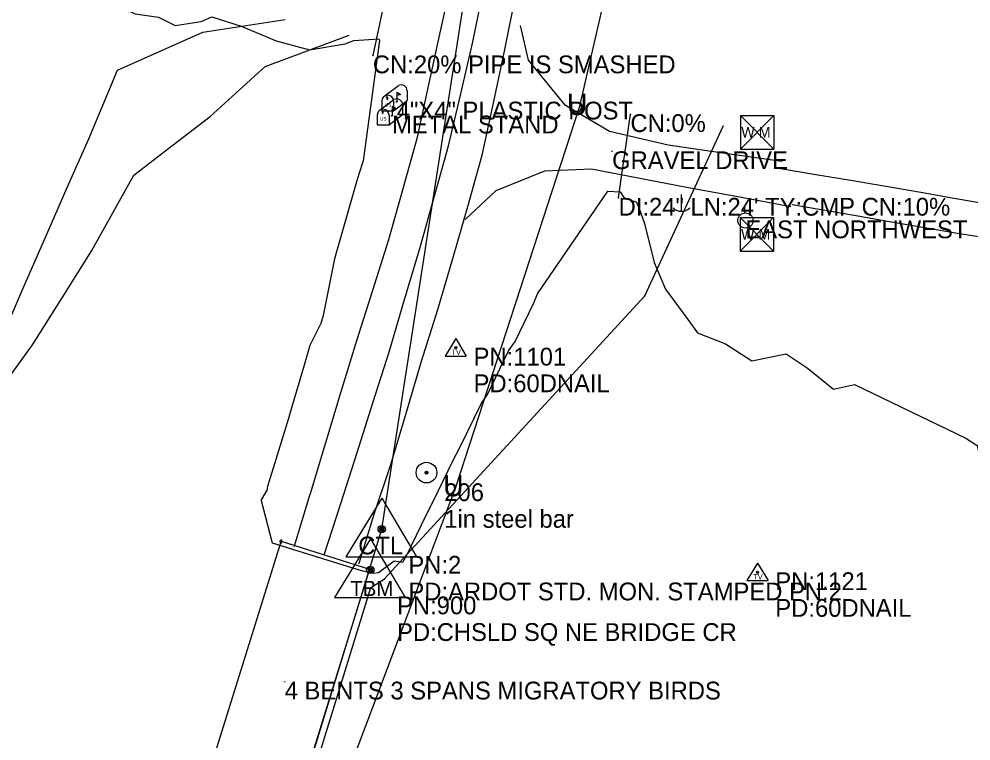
# Model space of a CAD drawing. Extents: x 1383673 to 1386849, y 1973501 to 1978801.
# Drawn here: x 1385039.6 to 1385307.2, y 1974767.7 to 1974970.6 of the extents above; entities that cross this region are included whole.
import ezdxf

# ---------------------------------------------------------------- set-up
doc = ezdxf.new("R2010")
doc.units = 0
for name, color, linetype in [('56', 7, 'Continuous'), ('8', 7, 'Continuous'), ('B-Super-Deck', 7, 'Continuous'), ('Default', 7, 'Continuous'), ('Level 42', 7, 'Continuous'), ('Level 6', 7, 'Continuous'), ('Level 62', 7, 'Continuous'), ('Level 8', 7, 'Continuous'), ('MOT_Barrier Wall Stage 3', 7, 'Continuous'), ('MOT_Drums_Stage 1', 7, 'Continuous'), ('MOT_Stage 2_Grading Hatch', 7, 'Continuous'), ('MOT_Stage 2_Pavement Hatch', 7, 'Continuous'), ('MOT_TIAB_Stage 3', 7, 'Continuous'), ('P_TC_Signs_Permanent', 7, 'Continuous'), ('R_Annotation', 7, 'Continuous'), ('R_Draft', 7, 'Continuous'), ('R_Guardrail', 7, 'Continuous'), ('R_Horz Alg', 7, 'Continuous'), ('R_Horz Alg Stationing', 7, 'Continuous'), ('R_Proposed Const Limits', 7, 'Continuous'), ('R_Traffic Signs', 7, 'Continuous'), ('S_BRIDGE', 7, 'Continuous'), ('S_EDGE_PAVEMENT', 7, 'Continuous'), ('S_STREAM', 7, 'Continuous'), ('S_WATER_UTILITIES', 7, 'Continuous'), ('SIGNS', 7, 'Continuous'), ('SIGNS_TX', 7, 'Continuous')]:
    doc.layers.add(name, color=color, linetype=linetype)

msp = doc.modelspace()

# ---------------------------------------------------------------- linework, layer by layer
at = {"layer": '56'}
for p, q in [((1385225.77, 1974921.3), (1385225.77, 1974916.57)), ((1385243.68, 1974916.15), (1385243.68, 1974918.26))]:
    msp.add_line(p, q, dxfattribs=at)
msp.add_circle((1385243.8, 1974914.01), 2.13, dxfattribs=at)
msp.add_arc((1385225.83, 1974920), 3.41, 226.3972, 313.6028, dxfattribs=at)
at = {"layer": '8'}
for points in [[(1385113.31, 1974823.83), (1385113.31, 1974824.33), (1385113.31, 1974823.83), (1385112.81, 1974823.83), (1385113.31, 1974823.83), (1385113.31, 1974823.33), (1385113.31, 1974823.83), (1385113.81, 1974823.83)], [(1385113.31, 1974823.73), (1385113.31, 1974824.23), (1385113.31, 1974823.73), (1385112.81, 1974823.73), (1385113.31, 1974823.73), (1385113.31, 1974823.23), (1385113.31, 1974823.73), (1385113.81, 1974823.73)], [(1385138.17, 1974815.97), (1385138.17, 1974816.47), (1385138.17, 1974815.97), (1385137.67, 1974815.97), (1385138.17, 1974815.97), (1385138.17, 1974815.47), (1385138.17, 1974815.97), (1385138.67, 1974815.97)]]:
    msp.add_lwpolyline(points, dxfattribs=at)
at = {"layer": 'B-Super-Deck'}
msp.add_lwpolyline([(1385125.5, 1974820.2), (1385125.52, 1974820.28), (1385125.52, 1974820.28), (1385130.06, 1974834.4), (1385130.08, 1974834.48), (1385134.67, 1974848.76), (1385139.2, 1974863.06), (1385143.72, 1974877.37), (1385147.99, 1974891.75), (1385152.25, 1974906.13), (1385156.31, 1974920.57), (1385160.37, 1974935.01), (1385163.79, 1974949.62), (1385167.22, 1974964.22), (1385170.2, 1974978.92)], dxfattribs=at)
at = {"layer": 'Level 42'}
for p, q in [((1385142.16, 1974948.83), (1385146.3, 1974951.93)), ((1385145.78, 1974950.11), (1385145.78, 1974947.4)), ((1385148.73, 1974950.46), (1385148.73, 1974947.75)), ((1385140.87, 1974944.89), (1385145, 1974948)), ((1385141.61, 1974947.55), (1385141.61, 1974944.84)), ((1385144.93, 1974944.84), (1385148.73, 1974947.75)), ((1385144.93, 1974947.55), (1385144.93, 1974944.84)), ((1385141.61, 1974944.84), (1385144.93, 1974944.84)), ((1385144.48, 1974946.18), (1385144.48, 1974943.47)), ((1385147.43, 1974946.53), (1385147.43, 1974943.81)), ((1385140.31, 1974943.62), (1385140.31, 1974940.9)), ((1385143.64, 1974940.9), (1385147.43, 1974943.81)), ((1385143.64, 1974943.62), (1385143.64, 1974940.9)), ((1385140.31, 1974940.9), (1385143.64, 1974940.9))]:
    msp.add_line(p, q, dxfattribs=at)
for points in [[(1385145.78, 1974950.11), (1385146.89, 1974949.45), (1385145.78, 1974949.1)], [(1385142.79, 1974948.67), (1385143.02, 1974948.53), (1385143.02, 1974948.14), (1385143.32, 1974948.14), (1385143.32, 1974948.5), (1385143.13, 1974948.75), (1385142.79, 1974948.69)], [(1385141.5, 1974944.73), (1385141.72, 1974944.6), (1385141.72, 1974944.21), (1385142.02, 1974944.21), (1385142.02, 1974944.57), (1385141.83, 1974944.82), (1385141.5, 1974944.76)], [(1385144.48, 1974946.18), (1385145.59, 1974945.52), (1385144.48, 1974945.17)]]:
    msp.add_lwpolyline(points, dxfattribs=at)
for centre, end in [((1385147.07, 1974950.46), 117.5718), ((1385143.27, 1974947.55), 180), ((1385145.77, 1974946.53), 117.5718), ((1385141.97, 1974943.62), 180)]:
    msp.add_arc(centre, 1.66, 0, end, dxfattribs=at)
for centre in [(1385145.78, 1974947.4), (1385144.48, 1974943.47)]:
    msp.add_ellipse(centre, major_axis=(0.145, 0.132), ratio=0.564646, dxfattribs=at)
at = {"layer": 'Level 6'}
for p, q in [((1385141.57, 1974827.22), (1385220.94, 1975337.61)), ((1385052.41, 1974536.57), (1385141.57, 1974827.22))]:
    msp.add_line(p, q, dxfattribs=at)
at = {"layer": 'Level 8'}
for p, q in [((1385162.4, 1974880.84), (1385159.39, 1974875.89)), ((1385162.4, 1974880.84), (1385165.35, 1974875.89)), ((1385159.39, 1974875.89), (1385165.35, 1974875.89)), ((1385247.21, 1974817.7), (1385244.2, 1974812.75)), ((1385247.21, 1974817.7), (1385250.16, 1974812.75)), ((1385244.2, 1974812.75), (1385250.16, 1974812.75))]:
    msp.add_line(p, q, dxfattribs=at)
for centre, radius in [((1385162.4, 1974878.23), 0.311), ((1385162.4, 1974878.23), 0.183), ((1385162.4, 1974878.23), 0.103), ((1385247.21, 1974815.09), 0.311), ((1385247.21, 1974815.09), 0.183), ((1385247.21, 1974815.09), 0.103)]:
    msp.add_circle(centre, radius, dxfattribs=at)
at = {"layer": 'MOT_Barrier Wall Stage 3'}
for radius in [2.91, 0.411, 0.262, 0.212, 0.145, 0.0822, 0.0581]:
    msp.add_circle((1385154.16, 1974843.12), radius, dxfattribs=at)
at = {"layer": 'MOT_Stage 2_Pavement Hatch'}
for points in [[(1385206.33, 1974933.45), (1385206.33, 1974933.5), (1385206.33, 1974933.45), (1385206.28, 1974933.45), (1385206.33, 1974933.45), (1385206.33, 1974933.4), (1385206.33, 1974933.45), (1385206.38, 1974933.45)], [(1385114.29, 1974784.35), (1385114.29, 1974784.4), (1385114.29, 1974784.35), (1385114.24, 1974784.35), (1385114.29, 1974784.35), (1385114.29, 1974784.3), (1385114.29, 1974784.35), (1385114.34, 1974784.35)]]:
    msp.add_lwpolyline(points, dxfattribs=at)
at = {"layer": 'R_Annotation'}
for p, q in [((1385197.25, 1974946.18), (1385218.09, 1975036.49)), ((1385162.45, 1974839.02), (1385197.25, 1974946.18)), ((1385123.92, 1974737.09), (1385162.45, 1974839.02))]:
    msp.add_line(p, q, dxfattribs=at)
at = {"layer": 'R_Guardrail'}
for points in [[(1385254.14, 1974930.56), (1385238.11, 1974932.85), (1385222.08, 1974935.14), (1385205.62, 1974939.03), (1385193.22, 1974946.31), (1385182.84, 1974959.12), (1385180.62, 1974968.82)], [(1385256.61, 1974917.85), (1385241.71, 1974920.62), (1385226.82, 1974923.38), (1385213.68, 1974925.89), (1385200.55, 1974928.4), (1385187.35, 1974927.86), (1385173.63, 1974922.32), (1385165.01, 1974914.24)], [(1385253.7, 1974928.65), (1385263.55, 1974926.95), (1385273.42, 1974925.32), (1385283.28, 1974923.62), (1385293.13, 1974921.93), (1385302.99, 1974920.23), (1385312.84, 1974918.54), (1385322.7, 1974916.85), (1385332.62, 1974915.52), (1385342.52, 1974914.09), (1385352.5, 1974913.13), (1385362.36, 1974911.44), (1385372.28, 1974910.15), (1385382.26, 1974909.13), (1385392.21, 1974907.91), (1385402.21, 1974907.04), (1385412.07, 1974905.38), (1385422.03, 1974904.26), (1385432.01, 1974903.3), (1385441.93, 1974901.97), (1385451.78, 1974900.24), (1385461.63, 1974898.52)], [(1385256.94, 1974918.46), (1385264.55, 1974917.17), (1385274.41, 1974915.48), (1385284.26, 1974913.76), (1385294.11, 1974912.07), (1385303.97, 1974910.38), (1385313.86, 1974908.87), (1385323.76, 1974907.42), (1385333.65, 1974905.97), (1385343.56, 1974904.56), (1385353.42, 1974902.88), (1385363.36, 1974901.69), (1385373.22, 1974899.99), (1385383.19, 1974898.98), (1385393.07, 1974897.55), (1385403.01, 1974896.28), (1385412.95, 1974895.09), (1385422.84, 1974893.61), (1385432.7, 1974891.89), (1385442.55, 1974890.17), (1385452.4, 1974888.44), (1385459.07, 1974887.27)]]:
    msp.add_lwpolyline(points, dxfattribs=at)
at = {"layer": 'R_Horz Alg'}
for points in [[(1385139.09, 1974960.39), (1385139.09, 1974960.44), (1385139.09, 1974960.39), (1385139.04, 1974960.39), (1385139.09, 1974960.39), (1385139.09, 1974960.34), (1385139.09, 1974960.39), (1385139.14, 1974960.39)], [(1385211.48, 1974943.88), (1385211.48, 1974943.93), (1385211.48, 1974943.88), (1385211.43, 1974943.88), (1385211.48, 1974943.88), (1385211.48, 1974943.83), (1385211.48, 1974943.88), (1385211.53, 1974943.88)], [(1385208.16, 1974920.37), (1385208.16, 1974920.42), (1385208.16, 1974920.37), (1385208.11, 1974920.37), (1385208.16, 1974920.37), (1385208.16, 1974920.32), (1385208.16, 1974920.37), (1385208.21, 1974920.37)]]:
    msp.add_lwpolyline(points, dxfattribs=at)
at = {"layer": 'R_Horz Alg Stationing'}
for points in [[(1385237.53, 1974940.55), (1385237.53, 1974940.6), (1385237.53, 1974940.55), (1385237.48, 1974940.55), (1385237.53, 1974940.55), (1385237.53, 1974940.5), (1385237.53, 1974940.55), (1385237.58, 1974940.55)], [(1385215.53, 1974892.83), (1385215.53, 1974892.88), (1385215.53, 1974892.83), (1385215.48, 1974892.83), (1385215.53, 1974892.83), (1385215.53, 1974892.78), (1385215.53, 1974892.83), (1385215.58, 1974892.83)], [(1385138.55, 1974810.81), (1385138.55, 1974810.86), (1385138.55, 1974810.81), (1385138.5, 1974810.81), (1385138.55, 1974810.81), (1385138.55, 1974810.76), (1385138.55, 1974810.81), (1385138.6, 1974810.81)], [(1385142.23, 1974813.14), (1385142.23, 1974813.19), (1385142.23, 1974813.14), (1385142.18, 1974813.14), (1385142.23, 1974813.14), (1385142.23, 1974813.09), (1385142.23, 1974813.14), (1385142.28, 1974813.14)]]:
    msp.add_lwpolyline(points, dxfattribs=at)
at = {"layer": 'R_Proposed Const Limits'}
for points in [[(1385033.77, 1974878.78), (1385040.46, 1974894.15), (1385047.15, 1974909.53), (1385053.2, 1974923.25), (1385059.25, 1974936.97), (1385067.3, 1974956.31), (1385079.28, 1974961.64), (1385091.25, 1974966.97), (1385114.48, 1974970.5)], [(1385033.23, 1974865), (1385043.39, 1974879.04), (1385051.72, 1974892.3), (1385060.05, 1974905.56), (1385071.88, 1974926.72), (1385082.61, 1974934.99), (1385093.33, 1974943.26), (1385108.8, 1974957.31), (1385120.59, 1974961.73), (1385132.39, 1974966.15)]]:
    msp.add_lwpolyline(points, dxfattribs=at)
at = {"layer": 'R_Traffic Signs'}
for p, q in [((1385147.06, 1974997.83), (1385139.09, 1974960.39)), ((1385208.16, 1974920.37), (1385211.48, 1974943.88))]:
    msp.add_line(p, q, dxfattribs=at)
at = {"layer": 'S_BRIDGE'}
for p, q in [((1385092.84, 1974758.05), (1385113.31, 1974823.73)), ((1385113.31, 1974823.83), (1385138.17, 1974815.97)), ((1385138.17, 1974815.97), (1385117.81, 1974750.35))]:
    msp.add_line(p, q, dxfattribs=at)
at = {"layer": 'S_EDGE_PAVEMENT'}
for points in [[(1385116.99, 1974822.37), (1385117.06, 1974822.57), (1385121.35, 1974836.74), (1385121.51, 1974837.24), (1385125.9, 1974851.58), (1385130.22, 1974865.91), (1385134.55, 1974880.27), (1385139.03, 1974894.4), (1385143.57, 1974908.7), (1385147.59, 1974923.02), (1385151.65, 1974937.46), (1385154.76, 1974951.73), (1385157.95, 1974966.39), (1385161.06, 1974980.78)], [(1385135.13, 1974817.49), (1385135.2, 1974817.71), (1385139.46, 1974831.47), (1385144.19, 1974845.7), (1385148.53, 1974860.11), (1385152.79, 1974874.5), (1385157.37, 1974888.97), (1385161.6, 1974903.36), (1385165.75, 1974917.92), (1385169.81, 1974932.36), (1385173.08, 1974947.44), (1385176.19, 1974962.12), (1385179.2, 1974977.1)]]:
    msp.add_lwpolyline(points, dxfattribs=at)
at = {"layer": 'S_STREAM'}
for p, q in [((1385140.98, 1974964.56), (1385136.39, 1974930.78)), ((1385185.35, 1974893.42), (1385205.11, 1974922.27)), ((1385274.47, 1974867.92), (1385305.77, 1974852.85))]:
    msp.add_line(p, q, dxfattribs=at)
for points in [[(1385046.87, 1974983.85), (1385046.94, 1974983.81), (1385054.66, 1974980.34), (1385059.54, 1974977.95), (1385067.7, 1974974.3), (1385072.23, 1974972.08), (1385078.82, 1974971.13), (1385083.49, 1974968.82), (1385090.87, 1974969.93), (1385093.85, 1974971.26), (1385102.02, 1974968.61), (1385111.91, 1974964.55), (1385120.22, 1974962.26), (1385120.8, 1974962.19), (1385121.03, 1974961.95), (1385121.25, 1974961.98), (1385131.32, 1974963.71), (1385133.73, 1974964.61), (1385140.76, 1974965.09), (1385140.98, 1974964.56)], [(1385136.39, 1974930.78), (1385135.13, 1974927), (1385134.26, 1974924.19), (1385129.06, 1974905.84), (1385128.98, 1974905.57), (1385128.33, 1974903.27), (1385125.13, 1974887.25), (1385124.48, 1974885.07), (1385121.4, 1974878.85), (1385119.59, 1974872.69), (1385116.54, 1974862.32), (1385115.28, 1974858.03), (1385109.47, 1974839.18), (1385109.24, 1974838.17), (1385107.67, 1974835.44), (1385107.69, 1974835.28)], [(1385205.11, 1974922.27), (1385208.56, 1974922.05), (1385209.65, 1974920.48), (1385213.17, 1974919.12), (1385213.98, 1974917.4), (1385215.46, 1974913.16), (1385218.2, 1974902.17), (1385221.32, 1974894.69), (1385227.62, 1974886.14), (1385230.38, 1974882.4), (1385238.17, 1974879.32), (1385245.58, 1974874.52), (1385255.24, 1974876.54), (1385261.13, 1974872.57), (1385268.6, 1974866.59), (1385274.47, 1974867.92)], [(1385133.35, 1974816.39), (1385136.21, 1974815.48), (1385137.27, 1974815.34), (1385139.3, 1974814.83), (1385140.67, 1974815.04), (1385145.08, 1974818.35), (1385147.53, 1974817.99), (1385148.63, 1974819.89), (1385154.15, 1974831.38), (1385156.08, 1974835.04), (1385161.68, 1974846.66), (1385163.52, 1974850.17), (1385169.49, 1974862.46), (1385171.29, 1974865.1), (1385177.21, 1974877.34), (1385179.07, 1974880.03), (1385184.31, 1974890.82), (1385185.35, 1974893.42)], [(1385305.77, 1974852.85), (1385308.99, 1974850.79), (1385312.25, 1974835.05), (1385312.84, 1974834.66), (1385313.19, 1974834.38), (1385326.49, 1974829.92), (1385339.4, 1974813.05), (1385339.67, 1974812.84), (1385339.9, 1974812.65), (1385345.36, 1974813.13), (1385352.7, 1974816.28), (1385356.16, 1974819.27), (1385357.62, 1974814.72), (1385369.96, 1974812.58), (1385377.46, 1974810.91)], [(1385107.69, 1974835.28), (1385110.75, 1974823.34), (1385133.35, 1974816.39)]]:
    msp.add_lwpolyline(points, dxfattribs=at)
at = {"layer": 'S_WATER_UTILITIES'}
for p, q in [((1385242.43, 1974943.55), (1385251.77, 1974943.55)), ((1385242.43, 1974943.55), (1385242.43, 1974934.06)), ((1385242.43, 1974943.55), (1385251.77, 1974934.06)), ((1385251.77, 1974943.55), (1385242.43, 1974934.06)), ((1385251.77, 1974943.55), (1385251.77, 1974934.06)), ((1385215.53, 1974892.83), (1385237.53, 1974940.55)), ((1385242.43, 1974934.06), (1385251.77, 1974934.06)), ((1385242.35, 1974914.87), (1385251.69, 1974914.87)), ((1385242.35, 1974914.87), (1385242.35, 1974905.37)), ((1385242.35, 1974914.87), (1385251.69, 1974905.37)), ((1385251.69, 1974914.87), (1385242.35, 1974905.37)), ((1385251.69, 1974914.87), (1385251.69, 1974905.37)), ((1385242.35, 1974905.37), (1385251.69, 1974905.37)), ((1385142.23, 1974813.14), (1385215.53, 1974892.83)), ((1385120.65, 1974752.73), (1385138.55, 1974810.81)), ((1385138.55, 1974810.81), (1385142.23, 1974813.14))]:
    msp.add_line(p, q, dxfattribs=at)
at = {"layer": 'SIGNS'}
for p, q in [((1385141.57, 1974835.92), (1385131.53, 1974819.41)), ((1385141.57, 1974835.92), (1385151.39, 1974819.41)), ((1385138.38, 1974824.5), (1385128.34, 1974807.98)), ((1385138.38, 1974824.5), (1385148.2, 1974807.98)), ((1385131.53, 1974819.41), (1385151.39, 1974819.41)), ((1385128.34, 1974807.98), (1385148.2, 1974807.98))]:
    msp.add_line(p, q, dxfattribs=at)
for centre, radius in [((1385141.57, 1974827.22), 1.04), ((1385141.57, 1974827.22), 0.609), ((1385141.57, 1974827.22), 0.344), ((1385138.38, 1974815.8), 1.04), ((1385138.38, 1974815.8), 0.609), ((1385138.38, 1974815.8), 0.344)]:
    msp.add_circle(centre, radius, dxfattribs=at)

# ---------------------------------------------------------------- texts
at = {"layer": 'Default'}
for p in [(1385193.62, 1974943.64), (1385158.82, 1974836.47)]:
    msp.add_text('U', height=6, dxfattribs=at).set_placement(p)
at = {"layer": 'Level 42'}
for p in [(1385142.37, 1974946.03), (1385141.08, 1974942.1)]:
    msp.add_text('US', height=0.96, dxfattribs=at).set_placement(p)
at = {"layer": 'Level 62'}
msp.add_text('EAST NORTHWEST', height=5, dxfattribs=at).set_placement((1385243.8, 1974909.01))
at = {"layer": 'Level 8'}
for p in [(1385161.2, 1974876.22), (1385246.01, 1974813.08)]:
    msp.add_text('TV', height=1.5, dxfattribs=at).set_placement(p)
at = {"layer": 'MOT_Drums_Stage 1'}
for s, p in [('4"X4" PLASTIC POST', (1385145.78, 1974942.4)), ('METAL STAND', (1385144.48, 1974938.47))]:
    msp.add_text(s, height=5, dxfattribs=at).set_placement(p)
at = {"layer": 'MOT_Stage 2_Grading Hatch'}
for s, p in [('GRAVEL DRIVE', (1385206.33, 1974928.45)), ('4 BENTS 3 SPANS MIGRATORY BIRDS', (1385114.29, 1974779.35))]:
    msp.add_text(s, height=5, dxfattribs=at).set_placement(p)
at = {"layer": 'MOT_TIAB_Stage 3'}
for s, p in [('206', (1385159.16, 1974835.12)), ('1in steel bar', (1385159.16, 1974827.62))]:
    msp.add_text(s, height=5, dxfattribs=at).set_placement(p)
at = {"layer": 'P_TC_Signs_Permanent'}
for s, p in [('CN:20% PIPE IS SMASHED', (1385139.09, 1974955.39)), ('CN:0%', (1385211.48, 1974938.88)), ('DI:24" LN:24\' TY:CMP CN:10%', (1385208.16, 1974915.37))]:
    msp.add_text(s, height=5, dxfattribs=at).set_placement(p)
at = {"layer": 'R_Draft'}
for s, p in [('PN:1101', (1385167.4, 1974873.23)), ('PD:60DNAIL', (1385167.4, 1974865.73)), ('PN:1121', (1385252.21, 1974810.09)), ('PD:60DNAIL', (1385252.21, 1974802.59))]:
    msp.add_text(s, height=5, dxfattribs=at).set_placement(p)
at = {"layer": 'S_WATER_UTILITIES'}
for p in [(1385242.63, 1974937.32), (1385242.56, 1974908.63)]:
    msp.add_text('W M', height=3, dxfattribs=at).set_placement(p)
at = {"layer": 'SIGNS'}
for s, height, p in [('CTL', 5, (1385134.98, 1974820.14)), ('TBM', 4.287, (1385132.73, 1974808.41))]:
    msp.add_text(s, height=height, dxfattribs=at).set_placement(p)
at = {"layer": 'SIGNS_TX'}
for s, p in [('PN:2', (1385149.07, 1974814.72)), ('PD:ARDOT STD. MON. STAMPED PN:2', (1385149.07, 1974807.22)), ('PN:900', (1385145.88, 1974803.3)), ('PD:CHSLD SQ NE BRIDGE CR', (1385145.88, 1974795.8))]:
    msp.add_text(s, height=5, dxfattribs=at).set_placement(p)

doc.saveas('drawing.dxf')
